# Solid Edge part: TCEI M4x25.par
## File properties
Title: 43200122ZN
Subject: Vite TCEI M4x25 zincata
Author: g_deluca
Template: RBuno.par
Last saved by: f_grande
Revision: 16
Application: Solid Edge
Company: EFFEBI S.p.A.
Codice: Codice
Indice rev.: Rev.
Data rev.: Data rev.
Firma rev.: Firma rev.
Descrizione rev.: Descrizione rev.
Densità: 7860,000 kg/m^3
Precisione: 0,990
Tipo di contenuto documento: 0
Document Number: UNI 5931
Material: Classe 8.8
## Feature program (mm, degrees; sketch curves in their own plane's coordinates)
sketch for "unnamed Protrusion 1" plane through (0, 0, 0) normal (0, 0, 1) x-axis (1, 0, 0)
extrude "unnamed Protrusion 1" add finite 4 along +normal
sketch for "ExtrudedProtrusion_3" plane through (0, 0, 0) normal (0, 0, 1) x-axis (1, 0, 0)
  circle centre (0, 0) radius 2
extrude "ExtrudedProtrusion_3" add finite 25 along -normal
sketch for "unnamed RevolvedCutout 1" plane through (0, 0, 0) normal (0, -1, 0) x-axis (1, 0, 0)
revolve "unnamed RevolvedCutout 1" cut full turn 360 deg about sketch line (0, -25) -> (0, -11)
sketch for "ExtrudedCutout_1" plane through (0, 0, 4) normal (0, 0, 1) x-axis (0, 1, 0)
  line (-1.5, 0.866) -> (-1.5, -0.866)
  line (-1.5, -0.866) -> (0, -1.7321)
  line (0, -1.7321) -> (1.5, -0.866)
  line (1.5, -0.866) -> (1.5, 0.866)
  line (1.5, 0.866) -> (0, 1.7321)
  line (0, 1.7321) -> (-1.5, 0.866)
extrude "ExtrudedCutout_1" cut finite 3 along -normal
chamfer "Chamfer_1" setback 0.25
thread "unnamed Thread 1"
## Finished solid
Body 1: solid body, 18 faces, 28 edges, 12 vertices.
  Faces by surface: plane 11, cylinder 4, cone 3
  Edges by curve: line 18, circle 10
Bounding box of the edges (mm): 7.000 x 7.000 x 29.000, from (-3.5, -3.5, -25) to (3.5, 3.5, 4).
Cylindrical faces by radius (mm): R1.995 x1, R2 x2, R3.5 x1
Conical faces (half-angle, radius in mm at the cone's reference point): 45 deg R1.75 x1, 45 deg R1.995 x1, 45 deg R3.5 x1
Planar faces by outward normal: +y 1, +z 3, -y 1, -z 2, oblique 4
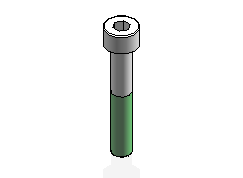
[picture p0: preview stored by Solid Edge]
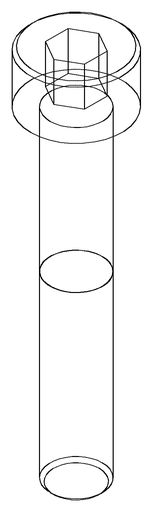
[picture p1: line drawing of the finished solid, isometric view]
